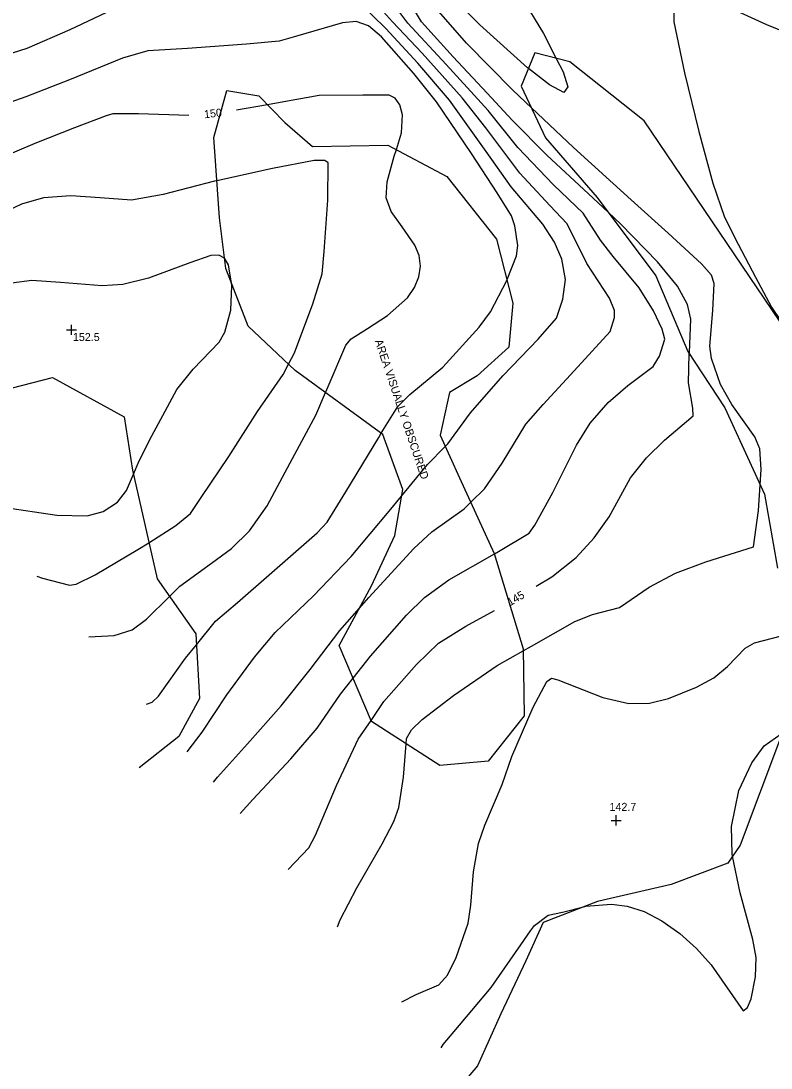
# Model space of a CAD drawing. Extents: x 1475150 to 2003689, y 770235 to 1112803.
# Drawn here: x 2001299.4 to 2001486.8, y 772314.6 to 772576.2 of the extents above; entities that cross this region are included whole.
import ezdxf

# ---------------------------------------------------------------- set-up
doc = ezdxf.new("R2010")
doc.units = 0
for name, color, linetype in [('RD_DTM_Major1', 7, 'Continuous'), ('RD_DTM_Major1_Lbl', 7, 'Continuous'), ('RD_DTM_Major2', 7, 'Continuous'), ('RD_DTM_Minor1', 7, 'Continuous'), ('RD_DTM_Minor2', 7, 'Continuous'), ('RD_DTM_Obscure', 7, 'Continuous'), ('RD_DTM_Spot_Elev', 7, 'Continuous'), ('RD_TX_Misc1', 7, 'Continuous')]:
    doc.layers.add(name, color=color, linetype=linetype)

msp = doc.modelspace()

# ---------------------------------------------------------------- linework, layer by layer
at = {"layer": 'RD_DTM_Major1'}
for points in [[(2001446.09, 772528.38), (2001441.16, 772533), (2001430.75, 772542.64), (2001422.1, 772551.44), (2001415.91, 772558.16), (2001407.38, 772567.22), (2001399.46, 772575.95), (2001396.1, 772581.64), (2001391.32, 772587.6), (2001380.34, 772597.51), (2001372.05, 772606.26), (2001364.43, 772615.94), (2001356.38, 772625.77), (2001351.67, 772629.86), (2001342.41, 772636.51), (2001333.46, 772642.78), (2001331.37, 772642.92), (2001329.18, 772641.91), (2001326.78, 772639.91), (2001323.1, 772635.42), (2001317.92, 772628.32), (2001315.04, 772626.08), (2001307.51, 772621.87), (2001299.88, 772618.23)], [(2001393.2, 772544.06), (2001394.49, 772548.28), (2001394.7, 772552.7), (2001394.09, 772555.21), (2001392.91, 772556.89), (2001391.42, 772557.61), (2001384.78, 772557.64), (2001373.87, 772557.6), (2001365.04, 772555.97), (2001360.96, 772555.27)], [(2001341.33, 772552.53), (2001328.75, 772553), (2001322.36, 772552.97), (2001320.73, 772552.48), (2001312.82, 772549.46), (2001302.9, 772545.54), (2001288.15, 772539.36), (2001279.39, 772535.57), (2001271.99, 772533.59), (2001263.2, 772531.63), (2001261.68, 772531.12)], [(2001428.08, 772434.96), (2001432.01, 772437.28), (2001438.09, 772442.16), (2001442.59, 772447.09), (2001446.31, 772452.31), (2001451.68, 772462.09), (2001455.7, 772467.05), (2001460.17, 772471.5), (2001467.29, 772477.54), (2001467.27, 772479.49), (2001466.19, 772485.77), (2001466.37, 772493.02)], [(2001336.5, 772432.43), (2001339.12, 772435.01), (2001346.97, 772440.73), (2001352, 772444.41), (2001356.53, 772448.84), (2001360.88, 772455.07), (2001366.64, 772465.82), (2001373.11, 772477.73), (2001375.47, 772483.33)], [(2001366.2, 772364.2), (2001371.35, 772369.58), (2001372.96, 772372.8), (2001378.22, 772385.17), (2001383.65, 772396.73), (2001386.88, 772401.45)]]:
    msp.add_lwpolyline(points, dxfattribs=at)
at = {"layer": 'RD_DTM_Major2'}
msp.add_line((2001360.96, 772555.27), (2001353.24, 772553.93), dxfattribs=at)
for points in [[(2001375.47, 772483.33), (2001376.14, 772484.9), (2001380.56, 772495.19), (2001381.93, 772496.76), (2001385.96, 772499.38), (2001390.99, 772502.62), (2001396.01, 772507.06), (2001397.75, 772509.6), (2001398.83, 772512.26), (2001399.2, 772514.96), (2001398.85, 772517.62), (2001397.8, 772520.16), (2001394.61, 772524.77), (2001391.87, 772528.59), (2001390.65, 772532.02), (2001390.87, 772535.99), (2001392.68, 772542.37), (2001393.2, 772544.06)], [(2001466.37, 772493.02), (2001466.38, 772493.34), (2001466.78, 772501.67), (2001465.91, 772505.39), (2001463.39, 772509.95), (2001458.4, 772516.02), (2001449.24, 772525.43), (2001446.09, 772528.38)], [(2001316.33, 772422.33), (2001322.66, 772422.68), (2001327.19, 772424.1), (2001330.76, 772426.76), (2001336.5, 772432.43)], [(2001386.88, 772401.45), (2001390.1, 772406.15), (2001398.18, 772415.44), (2001403.75, 772420.75), (2001410.51, 772424.96), (2001417.7, 772428.95)]]:
    msp.add_lwpolyline(points, dxfattribs=at)
at = {"layer": 'RD_DTM_Minor1'}
for points in [[(2001426.17, 772564.29), (2001425.94, 772564.47), (2001414.02, 772575.21), (2001404.38, 772584.88), (2001396.5, 772593.71), (2001392.19, 772598.39), (2001383.84, 772607.2), (2001376.41, 772614.68), (2001367.62, 772623.36), (2001350.9, 772639.44), (2001338.18, 772650.53), (2001328.64, 772658.51), (2001324.53, 772661.55), (2001321.08, 772663.04), (2001317.66, 772663.23), (2001312.3, 772662.97), (2001304.46, 772664.47), (2001301.58, 772663.11), (2001300.72, 772662.47)], [(2001426.92, 772554.5), (2001422.25, 772558.9), (2001410.72, 772570.65), (2001403.25, 772579.21), (2001395.44, 772589.27), (2001385.77, 772598.21), (2001376.71, 772608.9), (2001367.53, 772618.98), (2001356.43, 772629.93), (2001346.92, 772638.38), (2001337.21, 772645.94), (2001329.23, 772652.06), (2001326.72, 772653.3), (2001324.28, 772653.82), (2001321.88, 772653.67), (2001319.52, 772652.93), (2001314.87, 772650.09), (2001305.4, 772641.74), (2001303.38, 772639.93), (2001298.2, 772636.76)], [(2001405.4, 772469.87), (2001406.07, 772470.55), (2001411.67, 772478.25), (2001419.79, 772487.54), (2001428.58, 772496.71), (2001433.2, 772501.9), (2001434.79, 772506.69), (2001435.44, 772511.64), (2001434.53, 772516.64), (2001432.7, 772520.93), (2001429.76, 772525.43), (2001421.9, 772534.71), (2001415.64, 772543.61), (2001406.47, 772556.37), (2001398.58, 772565.62), (2001390.59, 772574.3), (2001380.72, 772584)], [(2001325.17, 772580.36), (2001311.63, 772573.95), (2001300.84, 772569.33), (2001288.2, 772565.3), (2001274.85, 772561.6), (2001271.65, 772560.99), (2001258.75, 772560.3), (2001248.11, 772559.02), (2001240.32, 772556.85), (2001229.27, 772552.77), (2001223.69, 772550.03), (2001215.33, 772544.58)], [(2001411.77, 772455.95), (2001415.2, 772459.32), (2001419.59, 772465.73), (2001425.5, 772475.48), (2001429.85, 772480.34), (2001437.61, 772488.81), (2001446.58, 772498.6), (2001447.71, 772502.12), (2001447.69, 772503.83), (2001446.39, 772506.96), (2001440.78, 772515.58), (2001435.87, 772525.5), (2001431.52, 772530.1), (2001423.99, 772538.18), (2001415.54, 772549.46), (2001409.62, 772556.97), (2001399.6, 772568.17), (2001392.26, 772575.97), (2001388.48, 772580.17)], [(2001424.4, 772582.3), (2001429.92, 772573.08), (2001433.11, 772566.84)], [(2001462.51, 772580.36), (2001462.51, 772575.93), (2001465.14, 772563.2), (2001468.72, 772548.54), (2001472.2, 772535.64), (2001475.15, 772527.21), (2001478.58, 772520.41), (2001482.89, 772512.22), (2001486.9, 772504.69), (2001494.48, 772493.42), (2001504.23, 772480.89), (2001511.56, 772472.81), (2001516.58, 772468.35), (2001519.31, 772464.15), (2001523.12, 772458.05), (2001531.85, 772446.63), (2001538.68, 772437.78), (2001545.63, 772428.63), (2001552.47, 772420.41), (2001563.03, 772408.98), (2001564.78, 772405.72), (2001569.85, 772394.63), (2001573.16, 772388.63)], [(2001501.32, 772568.85), (2001485.75, 772575.25), (2001472.28, 772581.42)], [(2001417.69, 772443.06), (2001418.73, 772443.65), (2001426.4, 772448.23), (2001427.77, 772450.21), (2001432.25, 772458.37), (2001438.22, 772470.21), (2001441.57, 772475.74), (2001446.12, 772480.89), (2001450.97, 772485.15), (2001457.37, 772489.83), (2001458.9, 772492.43), (2001460.23, 772496.71), (2001459.56, 772499.19), (2001457.39, 772503.78), (2001453.87, 772509.49), (2001447.32, 772517.33), (2001444.14, 772521.39), (2001439.85, 772528.17), (2001432.43, 772535.23), (2001423.49, 772544.6), (2001416.08, 772553.78), (2001405.67, 772565.28), (2001396.04, 772575.64), (2001393.08, 772579.65)], [(2001420.81, 772511.38), (2001420.9, 772511.56), (2001423.2, 772517.5), (2001423.49, 772520.11), (2001422.76, 772525.03), (2001421.93, 772527.5), (2001418.39, 772533.27), (2001411.94, 772543.08), (2001403.19, 772555.98), (2001397.56, 772563.05), (2001389.49, 772572.25), (2001386.19, 772574.96), (2001383.16, 772576.04), (2001379.77, 772575.73), (2001367.98, 772572.29), (2001363.94, 772571.17), (2001355.74, 772570.41), (2001341, 772569.33), (2001331.14, 772568.69), (2001324.79, 772566.88), (2001311.58, 772561.44), (2001300.66, 772557.27), (2001287.61, 772552.69)], [(2001348.37, 772536.27), (2001347.8, 772536.15), (2001334.9, 772532.84), (2001327.02, 772531.43), (2001319.19, 772531.99), (2001311.84, 772532.5), (2001305.02, 772532.03), (2001299.58, 772530.42), (2001290.23, 772526), (2001278.78, 772520.39), (2001265.64, 772514.96), (2001261.97, 772513.05)], [(2001350.28, 772516.94), (2001350.28, 772516.94), (2001348.82, 772517.67), (2001346.88, 772517.58), (2001341.61, 772515.78), (2001331.24, 772511.9), (2001324.9, 772510.32), (2001319.67, 772509.99), (2001309.33, 772510.85), (2001302.17, 772511.38), (2001297.07, 772510.69), (2001287.89, 772507.53), (2001281.44, 772505.61), (2001277.83, 772504.81), (2001274.71, 772503.04), (2001265.29, 772495.97), (2001263.94, 772494.64)], [(2001327.52, 772462.96), (2001328.96, 772466.31), (2001332.07, 772472.57), (2001335.45, 772478.73), (2001338.36, 772484.16), (2001342.42, 772489.23), (2001348.93, 772495.98), (2001350.34, 772498.46), (2001351.84, 772503.97), (2001352.12, 772509.98), (2001352.01, 772510.67)], [(2001331.38, 772445.85), (2001338.11, 772450.11), (2001341.74, 772453.15), (2001344.42, 772457.18), (2001351.35, 772467.35), (2001358.51, 772478.63), (2001364.92, 772487.89), (2001366.24, 772490.41)], [(2001343.23, 772420.37), (2001347.97, 772426.22), (2001353.53, 772430.95), (2001361.43, 772437.82), (2001373.43, 772448.35), (2001375.9, 772450.97), (2001380.59, 772458.55), (2001388.78, 772472.12), (2001389.42, 772473.18)], [(2001424.84, 772418.81), (2001426.92, 772419.97), (2001437.78, 772426.19), (2001442.2, 772427.92), (2001448.91, 772429.66), (2001456.37, 772434.77), (2001462.88, 772438.23), (2001470.47, 772441.03), (2001482.41, 772444.82), (2001483.66, 772453.92), (2001484.06, 772460.3)], [(2001340.94, 772393.64), (2001344.67, 772398.53), (2001350.87, 772407.81), (2001357.74, 772417.29), (2001362.94, 772423.44), (2001372.5, 772432.58), (2001381.9, 772442.4), (2001391.4, 772453.76), (2001394.5, 772457.5)], [(2001347.51, 772385.99), (2001348.53, 772387.28), (2001356.03, 772395.61), (2001364.38, 772405.08), (2001371.62, 772414.2), (2001379.03, 772423.92), (2001383.95, 772429.47)], [(2001394.52, 772331.19), (2001398.15, 772332.99), (2001403.77, 772335.39), (2001405.99, 772337.8), (2001408.14, 772342.22), (2001411.1, 772350.84), (2001411.75, 772355.33), (2001412.46, 772363.63), (2001413.7, 772370.68), (2001415.26, 772375.32), (2001419.6, 772385.46), (2001422.03, 772392.42), (2001427.38, 772404.76), (2001430.81, 772411.15), (2001431.97, 772411.98), (2001433.52, 772411.55), (2001444.79, 772407.19), (2001451.26, 772405.67), (2001456.38, 772405.8), (2001461.13, 772406.95), (2001468.2, 772409.72), (2001472.45, 772412.08), (2001475.9, 772414.88), (2001480.34, 772419.52), (2001482.68, 772420.82), (2001489.41, 772422.58)], [(2001354.21, 772378.18), (2001357.37, 772381.71), (2001366.8, 772391.85), (2001373.41, 772399.52), (2001379.27, 772408.01), (2001382.39, 772412)], [(2001477.15, 772367.51), (2001477.03, 772368.07), (2001476.94, 772374.92), (2001478.76, 772383.92), (2001482, 772390.88), (2001485.1, 772395.07), (2001489.27, 772398.12)], [(2001378.45, 772349.92), (2001379.17, 772351.66), (2001383.31, 772359.61), (2001389.65, 772370.62), (2001392.58, 772376.21), (2001393.77, 772379.66), (2001394.94, 772387.26), (2001395.62, 772395.61)], [(2001404.39, 772319.68), (2001404.9, 772320.5), (2001408.92, 772325.33), (2001416.84, 772334.75), (2001424.27, 772345.39), (2001426.69, 772348.85), (2001427.73, 772350.23), (2001431.08, 772352.8), (2001434.67, 772353.52), (2001440.25, 772354.96)]]:
    msp.add_lwpolyline(points, dxfattribs=at)
at = {"layer": 'RD_DTM_Minor2'}
for points in [[(2001433.11, 772566.84), (2001434.84, 772563.46), (2001435.98, 772559.7), (2001435.03, 772558.34), (2001431.41, 772560.2), (2001426.17, 772564.29)], [(2001484.06, 772460.3), (2001484.3, 772464.12), (2001484, 772469.29), (2001482.74, 772472.3), (2001476.96, 772480.37), (2001474.16, 772485.41), (2001471.9, 772491.9), (2001471.53, 772494.98), (2001472.28, 772503.82), (2001472.56, 772510.56), (2001471.94, 772512.65), (2001469.42, 772515.54), (2001461.06, 772523.21), (2001451.82, 772531.52), (2001437.46, 772544.58), (2001426.92, 772554.5)], [(2001366.24, 772490.41), (2001367.76, 772493.32), (2001372.35, 772505.49), (2001374.67, 772513), (2001375.14, 772518.56), (2001376.03, 772531.39), (2001376.13, 772540.75), (2001375.32, 772541.35), (2001372.68, 772541.31), (2001362.28, 772539.34), (2001348.37, 772536.27)], [(2001352.01, 772510.67), (2001351.28, 772515.27), (2001350.28, 772516.94)], [(2001389.42, 772473.18), (2001393.52, 772479.89), (2001396.53, 772482.89), (2001404.78, 772489.66), (2001413.88, 772499.66), (2001416.73, 772503.56), (2001420.81, 772511.38)], [(2001394.5, 772457.5), (2001400.99, 772465.36), (2001405.4, 772469.87)], [(2001290.73, 772455.85), (2001294.93, 772454.69), (2001308.39, 772452.7), (2001315.93, 772452.52), (2001319.91, 772453.63), (2001323.57, 772456.01), (2001325.77, 772458.86), (2001327.52, 772462.96)], [(2001383.95, 772429.47), (2001386.35, 772432.18), (2001397.56, 772444.37), (2001402.07, 772448.55), (2001410.11, 772454.31), (2001411.77, 772455.95)], [(2001303.36, 772437.45), (2001304.76, 772436.99), (2001311.57, 772435.21), (2001313.17, 772435.5), (2001317.92, 772437.81), (2001328.63, 772444.11), (2001331.38, 772445.85)], [(2001382.39, 772412), (2001386.71, 772417.52), (2001395.68, 772427.74), (2001400.22, 772432.18), (2001406.27, 772436.55), (2001417.69, 772443.06)], [(2001330.75, 772405.52), (2001332.21, 772406.02), (2001333.81, 772407.47), (2001340.49, 772417), (2001343.23, 772420.37)], [(2001395.62, 772395.61), (2001395.73, 772396.94), (2001396.98, 772399.12), (2001399.63, 772401.72), (2001407.43, 772407.66), (2001418.39, 772415.2), (2001424.84, 772418.81)], [(2001440.25, 772354.96), (2001440.53, 772355.03), (2001446.93, 772355.52), (2001450.82, 772355.02), (2001455.05, 772353.7), (2001459.53, 772351.37), (2001463.99, 772348.21), (2001468.17, 772344.47), (2001471.79, 772340.4), (2001479.81, 772328.92), (2001480.9, 772329.7), (2001481.79, 772331.86), (2001482.9, 772337.43), (2001483.09, 772342.21), (2001482.24, 772346.76), (2001479.06, 772358.37), (2001477.15, 772367.51)]]:
    msp.add_lwpolyline(points, dxfattribs=at)
at = {"layer": 'RD_DTM_Obscure'}
for points in [[(2001539.81, 772426.06), (2001455.07, 772551.2), (2001436.52, 772565.99), (2001427.74, 772568.19), (2001424.4, 772559.88), (2001430.45, 772546.99), (2001443.34, 772532.05), (2001458.03, 772512.49), (2001465.97, 772493.63), (2001475.23, 772479.53), (2001485.11, 772458), (2001488.41, 772439.49)], [(2001367.88, 772488.86), (2001356.13, 772499.98), (2001350.61, 772514.31), (2001349.03, 772527.01), (2001347.61, 772547.05), (2001350.8, 772558.82), (2001358.84, 772557.46), (2001365.32, 772550.78), (2001372.24, 772544.84), (2001391.06, 772545.2), (2001405.79, 772537.33), (2001418.2, 772521.68), (2001422.25, 772505.68), (2001421.25, 772494.7), (2001413.35, 772487.53), (2001406.46, 772483.38), (2001404.12, 772472.7), (2001408.96, 772462.05), (2001417.66, 772443.16), (2001424.83, 772419.33), (2001425.15, 772402.61), (2001416.16, 772391.24), (2001404.05, 772390.19), (2001387.01, 772401.15), (2001378.91, 772420.17), (2001387, 772435.1), (2001392.77, 772447.67), (2001394.79, 772459.16), (2001389.79, 772472.91), (2001367.88, 772488.86)], [(2001196.95, 772540.74), (2001216.8, 772544.89), (2001239.36, 772543.8), (2001257.05, 772537.08), (2001266.95, 772524.36), (2001259.27, 772506.93), (2001264.94, 772492), (2001284.65, 772481.26), (2001307.33, 772487.13), (2001325.18, 772477.3), (2001327.29, 772463.98), (2001333.42, 772436.8), (2001343.07, 772423.11), (2001344.01, 772406.94), (2001338.84, 772397.43), (2001328.95, 772389.62)], [(2001489.16, 772397.08), (2001479.03, 772370.25), (2001475.98, 772365.82), (2001461.81, 772360.46), (2001443.46, 772356.19), (2001429.89, 772350.98), (2001425.5, 772341.42), (2001419.28, 772328.12), (2001413.48, 772315.16), (2001406.48, 772306.95)]]:
    msp.add_lwpolyline(points, dxfattribs=at)
at = {"layer": 'RD_DTM_Spot_Elev'}
for p, q in [((2001310.77, 772499.02), (2001313.27, 772499.02)), ((2001312.02, 772497.77), (2001312.02, 772500.27)), ((2001446.88, 772376.49), (2001449.38, 772376.49)), ((2001448.13, 772375.24), (2001448.13, 772377.74))]:
    msp.add_line(p, q, dxfattribs=at)

# ---------------------------------------------------------------- texts
at = {"layer": 'RD_DTM_Major1_Lbl'}
for s, rotation, p in [('150', 6.3233, (2001345.26, 772551.86)), ('145', 30.561, (2001421.59, 772429.96))]:
    msp.add_text(s, height=2, rotation=rotation, dxfattribs=at).set_placement(p)
at = {"layer": 'RD_DTM_Spot_Elev'}
for s, p in [('152.5', (2001312.39, 772496.23)), ('142.7', (2001446.43, 772378.85))]:
    msp.add_text(s, height=2, dxfattribs=at).set_placement(p)
at = {"layer": 'RD_TX_Misc1'}
msp.add_text('AREA VISUALLY OBSCURED', height=2, rotation=288.5954, dxfattribs=at).set_placement((2001387.76, 772496.28))

doc.saveas('drawing.dxf')
